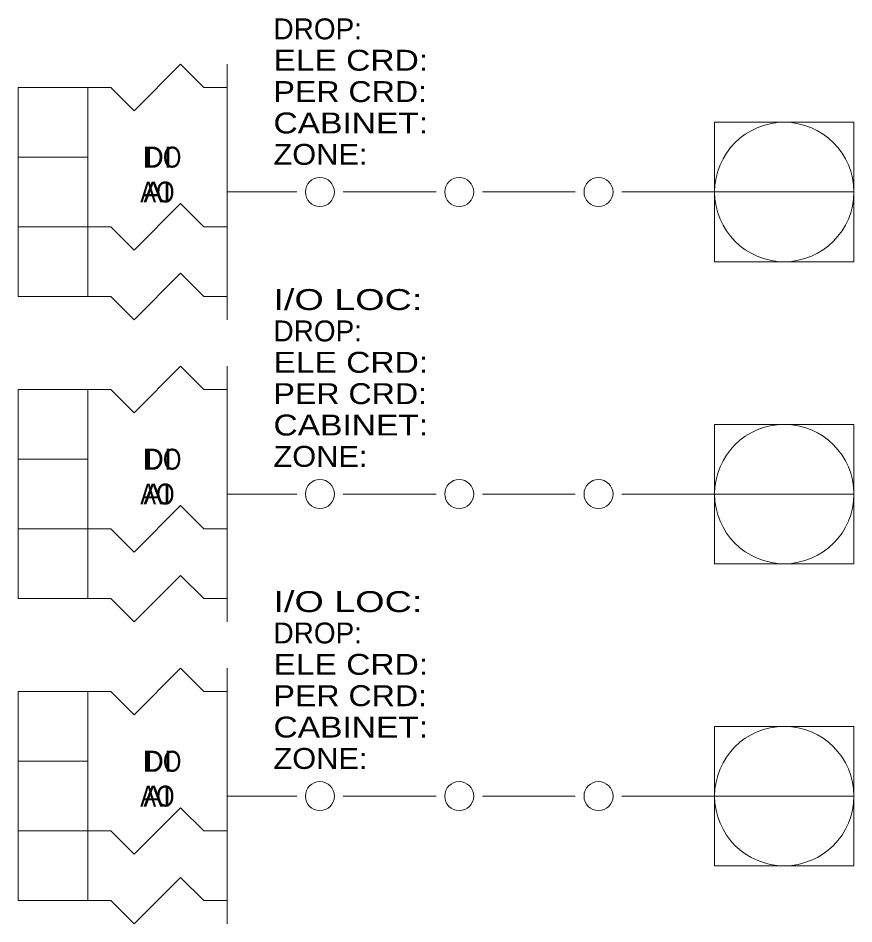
# Model space of a CAD drawing. Extents: x 0.01 to 1.26, y 0 to 0.83.
# Drawn here: x 0.9583 to 1.2583, y 0.1708 to 0.4957 of the extents above; entities that cross this region are included whole.
import ezdxf
from ezdxf.enums import TextEntityAlignment as Align

# ---------------------------------------------------------------- set-up
doc = ezdxf.new("R2010")
doc.units = 0
doc.header["$LTSCALE"] = 0.003
for name, color, linetype, lineweight in [('31', 7, 'Continuous', 13), ('32', 7, 'Continuous', 13), ('33', 7, 'Continuous', 13), ('34', 7, 'Continuous', 13), ('39', 7, 'Continuous', 13), ('40', 7, 'Continuous', 13), ('41', 7, 'Continuous', 13), ('42', 7, 'Continuous', 13), ('43', 7, 'Continuous', 13), ('44', 7, 'Continuous', 13), ('49', 7, 'Continuous', 13), ('50', 7, 'Continuous', 13), ('51', 7, 'Continuous', 13), ('52', 7, 'Continuous', 13), ('53', 7, 'Continuous', 13), ('54', 7, 'Continuous', 13), ('59', 7, 'Continuous', 13), ('60', 7, 'Continuous', 13)]:
    doc.layers.add(name, color=color, linetype=linetype, lineweight=lineweight)

msp = doc.modelspace()

# ---------------------------------------------------------------- linework, layer by layer
at = {"layer": '31'}
msp.add_line((1.033333, 0.479166), (1.033333, 0.4125), dxfattribs=at)
for points in [[(0.983333, 0.470833), (0.991666, 0.470833), (1, 0.4625), (1.016666, 0.479166), (1.025, 0.470833), (1.033333, 0.470833)], [(0.958333, 0.445833), (0.958333, 0.420833), (0.983333, 0.420833), (0.983333, 0.445833)], [(0.983333, 0.420833), (0.991666, 0.420833), (1, 0.4125), (1.016666, 0.429166), (1.025, 0.420833), (1.033333, 0.420833)]]:
    msp.add_lwpolyline(points, dxfattribs=at)
msp.add_lwpolyline([(0.958333, 0.470833), (0.983333, 0.470833), (0.983333, 0.445833), (0.958333, 0.445833)], close=True, dxfattribs=at)
at = {"layer": '32'}
for p, q in [((1.033333, 0.479166), (1.033333, 0.4125)), ((0.958333, 0.445833), (0.983333, 0.445833))]:
    msp.add_line(p, q, dxfattribs=at)
for points in [[(0.983333, 0.470833), (0.991666, 0.470833), (1, 0.4625), (1.016666, 0.479166), (1.025, 0.470833), (1.033333, 0.470833)], [(0.983333, 0.420833), (0.991666, 0.420833), (1, 0.4125), (1.016666, 0.429166), (1.025, 0.420833), (1.033333, 0.420833)]]:
    msp.add_lwpolyline(points, dxfattribs=at)
msp.add_lwpolyline([(0.958333, 0.470833), (0.983333, 0.470833), (0.983333, 0.420833), (0.958333, 0.420833)], close=True, dxfattribs=at)
at = {"layer": '33'}
for p, q in [((1.033333, 0.3875), (1.033333, 0.479166)), ((0.958333, 0.445833), (0.983333, 0.445833)), ((0.958333, 0.420833), (0.983333, 0.420833))]:
    msp.add_line(p, q, dxfattribs=at)
for points in [[(0.983333, 0.470833), (0.991666, 0.470833), (1, 0.4625), (1.016666, 0.479166), (1.025, 0.470833), (1.033333, 0.470833)], [(0.983333, 0.395833), (0.991666, 0.395833), (1, 0.3875), (1.016666, 0.404166), (1.025, 0.395833), (1.033333, 0.395833)]]:
    msp.add_lwpolyline(points, dxfattribs=at)
msp.add_lwpolyline([(0.958333, 0.470833), (0.983333, 0.470833), (0.983333, 0.395833), (0.958333, 0.395833)], close=True, dxfattribs=at)
at = {"layer": '34'}
for p, q in [((1.033333, 0.3875), (1.033333, 0.479166)), ((0.958333, 0.445833), (0.983333, 0.445833)), ((0.958333, 0.420833), (0.983333, 0.420833))]:
    msp.add_line(p, q, dxfattribs=at)
for points in [[(0.983333, 0.470833), (0.991666, 0.470833), (1, 0.4625), (1.016666, 0.479166), (1.025, 0.470833), (1.033333, 0.470833)], [(0.983333, 0.395833), (0.991666, 0.395833), (1, 0.3875), (1.016666, 0.404166), (1.025, 0.395833), (1.033333, 0.395833)]]:
    msp.add_lwpolyline(points, dxfattribs=at)
msp.add_lwpolyline([(0.958333, 0.470833), (0.983333, 0.470833), (0.983333, 0.395833), (0.958333, 0.395833)], close=True, dxfattribs=at)
at = {"layer": '39'}
for p, q in [((1.058333, 0.433333), (1.033333, 0.433333)), ((1.108333, 0.433333), (1.075, 0.433333)), ((1.158333, 0.433333), (1.125, 0.433333)), ((1.208333, 0.433333), (1.175, 0.433333)), ((1.208333, 0.433333), (1.258333, 0.433333))]:
    msp.add_line(p, q, dxfattribs=at)
msp.add_lwpolyline([(1.208333, 0.458333), (1.208333, 0.408333), (1.258333, 0.408333), (1.258333, 0.458333)], close=True, dxfattribs=at)
for centre, radius in [((1.233333, 0.433333), 0.025), ((1.066666, 0.433333), 0.005208), ((1.116666, 0.433333), 0.005208), ((1.166666, 0.433333), 0.005208)]:
    msp.add_circle(centre, radius, dxfattribs=at)
at = {"layer": '40'}
for p, q in [((1.058333, 0.433333), (1.033333, 0.433333)), ((1.108333, 0.433333), (1.075, 0.433333)), ((1.158333, 0.433333), (1.125, 0.433333)), ((1.208333, 0.433333), (1.175, 0.433333)), ((1.208333, 0.433333), (1.258333, 0.433333))]:
    msp.add_line(p, q, dxfattribs=at)
msp.add_lwpolyline([(1.208333, 0.458333), (1.208333, 0.408333), (1.258333, 0.408333), (1.258333, 0.458333)], close=True, dxfattribs=at)
for centre, radius in [((1.233333, 0.433333), 0.025), ((1.066666, 0.433333), 0.005208), ((1.116666, 0.433333), 0.005208), ((1.166666, 0.433333), 0.005208)]:
    msp.add_circle(centre, radius, dxfattribs=at)
at = {"layer": '41'}
msp.add_line((1.033333, 0.370833), (1.033333, 0.304166), dxfattribs=at)
for points in [[(0.983333, 0.3625), (0.991666, 0.3625), (1, 0.354166), (1.016666, 0.370833), (1.025, 0.3625), (1.033333, 0.3625)], [(0.958333, 0.3375), (0.958333, 0.3125), (0.983333, 0.3125), (0.983333, 0.3375)], [(0.983333, 0.3125), (0.991666, 0.3125), (1, 0.304166), (1.016666, 0.320833), (1.025, 0.3125), (1.033333, 0.3125)]]:
    msp.add_lwpolyline(points, dxfattribs=at)
msp.add_lwpolyline([(0.958333, 0.3625), (0.983333, 0.3625), (0.983333, 0.3375), (0.958333, 0.3375)], close=True, dxfattribs=at)
at = {"layer": '42'}
for p, q in [((1.033333, 0.370833), (1.033333, 0.304166)), ((0.958333, 0.3375), (0.983333, 0.3375))]:
    msp.add_line(p, q, dxfattribs=at)
for points in [[(0.983333, 0.3625), (0.991666, 0.3625), (1, 0.354166), (1.016666, 0.370833), (1.025, 0.3625), (1.033333, 0.3625)], [(0.983333, 0.3125), (0.991666, 0.3125), (1, 0.304166), (1.016666, 0.320833), (1.025, 0.3125), (1.033333, 0.3125)]]:
    msp.add_lwpolyline(points, dxfattribs=at)
msp.add_lwpolyline([(0.958333, 0.3625), (0.983333, 0.3625), (0.983333, 0.3125), (0.958333, 0.3125)], close=True, dxfattribs=at)
at = {"layer": '43'}
for p, q in [((1.033333, 0.279166), (1.033333, 0.370833)), ((0.958333, 0.3375), (0.983333, 0.3375)), ((0.958333, 0.3125), (0.983333, 0.3125))]:
    msp.add_line(p, q, dxfattribs=at)
for points in [[(0.983333, 0.3625), (0.991666, 0.3625), (1, 0.354166), (1.016666, 0.370833), (1.025, 0.3625), (1.033333, 0.3625)], [(0.983333, 0.2875), (0.991666, 0.2875), (1, 0.279166), (1.016666, 0.295833), (1.025, 0.2875), (1.033333, 0.2875)]]:
    msp.add_lwpolyline(points, dxfattribs=at)
msp.add_lwpolyline([(0.958333, 0.3625), (0.983333, 0.3625), (0.983333, 0.2875), (0.958333, 0.2875)], close=True, dxfattribs=at)
at = {"layer": '44'}
for p, q in [((1.033333, 0.279166), (1.033333, 0.370833)), ((0.958333, 0.3375), (0.983333, 0.3375)), ((0.958333, 0.3125), (0.983333, 0.3125))]:
    msp.add_line(p, q, dxfattribs=at)
for points in [[(0.983333, 0.3625), (0.991666, 0.3625), (1, 0.354166), (1.016666, 0.370833), (1.025, 0.3625), (1.033333, 0.3625)], [(0.983333, 0.2875), (0.991666, 0.2875), (1, 0.279166), (1.016666, 0.295833), (1.025, 0.2875), (1.033333, 0.2875)]]:
    msp.add_lwpolyline(points, dxfattribs=at)
msp.add_lwpolyline([(0.958333, 0.3625), (0.983333, 0.3625), (0.983333, 0.2875), (0.958333, 0.2875)], close=True, dxfattribs=at)
at = {"layer": '49'}
for p, q in [((1.058333, 0.325), (1.033333, 0.325)), ((1.108333, 0.325), (1.075, 0.325)), ((1.158333, 0.325), (1.125, 0.325)), ((1.208333, 0.325), (1.175, 0.325)), ((1.208333, 0.325), (1.258333, 0.325))]:
    msp.add_line(p, q, dxfattribs=at)
msp.add_lwpolyline([(1.208333, 0.35), (1.208333, 0.3), (1.258333, 0.3), (1.258333, 0.35)], close=True, dxfattribs=at)
for centre, radius in [((1.233333, 0.325), 0.025), ((1.066666, 0.325), 0.005208), ((1.116666, 0.325), 0.005208), ((1.166666, 0.325), 0.005208)]:
    msp.add_circle(centre, radius, dxfattribs=at)
at = {"layer": '50'}
for p, q in [((1.058333, 0.325), (1.033333, 0.325)), ((1.108333, 0.325), (1.075, 0.325)), ((1.158333, 0.325), (1.125, 0.325)), ((1.208333, 0.325), (1.175, 0.325)), ((1.208333, 0.325), (1.258333, 0.325))]:
    msp.add_line(p, q, dxfattribs=at)
msp.add_lwpolyline([(1.208333, 0.35), (1.208333, 0.3), (1.258333, 0.3), (1.258333, 0.35)], close=True, dxfattribs=at)
for centre, radius in [((1.233333, 0.325), 0.025), ((1.066666, 0.325), 0.005208), ((1.116666, 0.325), 0.005208), ((1.166666, 0.325), 0.005208)]:
    msp.add_circle(centre, radius, dxfattribs=at)
at = {"layer": '51'}
msp.add_line((1.033333, 0.2625), (1.033333, 0.195833), dxfattribs=at)
for points in [[(0.983333, 0.254166), (0.991666, 0.254166), (1, 0.245833), (1.016666, 0.2625), (1.025, 0.254166), (1.033333, 0.254166)], [(0.958333, 0.229166), (0.958333, 0.204166), (0.983333, 0.204166), (0.983333, 0.229166)], [(0.983333, 0.204166), (0.991666, 0.204166), (1, 0.195833), (1.016666, 0.2125), (1.025, 0.204166), (1.033333, 0.204166)]]:
    msp.add_lwpolyline(points, dxfattribs=at)
msp.add_lwpolyline([(0.958333, 0.254166), (0.983333, 0.254166), (0.983333, 0.229166), (0.958333, 0.229166)], close=True, dxfattribs=at)
at = {"layer": '52'}
for p, q in [((1.033333, 0.2625), (1.033333, 0.195833)), ((0.958333, 0.229166), (0.983333, 0.229166))]:
    msp.add_line(p, q, dxfattribs=at)
for points in [[(0.983333, 0.254166), (0.991666, 0.254166), (1, 0.245833), (1.016666, 0.2625), (1.025, 0.254166), (1.033333, 0.254166)], [(0.983333, 0.204166), (0.991666, 0.204166), (1, 0.195833), (1.016666, 0.2125), (1.025, 0.204166), (1.033333, 0.204166)]]:
    msp.add_lwpolyline(points, dxfattribs=at)
msp.add_lwpolyline([(0.958333, 0.254166), (0.983333, 0.254166), (0.983333, 0.204166), (0.958333, 0.204166)], close=True, dxfattribs=at)
at = {"layer": '53'}
for p, q in [((1.033333, 0.170833), (1.033333, 0.2625)), ((0.958333, 0.229166), (0.983333, 0.229166)), ((0.958333, 0.204166), (0.983333, 0.204166))]:
    msp.add_line(p, q, dxfattribs=at)
for points in [[(0.983333, 0.254166), (0.991666, 0.254166), (1, 0.245833), (1.016666, 0.2625), (1.025, 0.254166), (1.033333, 0.254166)], [(0.983333, 0.179166), (0.991666, 0.179166), (1, 0.170833), (1.016666, 0.1875), (1.025, 0.179166), (1.033333, 0.179166)]]:
    msp.add_lwpolyline(points, dxfattribs=at)
msp.add_lwpolyline([(0.958333, 0.254166), (0.983333, 0.254166), (0.983333, 0.179166), (0.958333, 0.179166)], close=True, dxfattribs=at)
at = {"layer": '54'}
for p, q in [((1.033333, 0.170833), (1.033333, 0.2625)), ((0.958333, 0.229166), (0.983333, 0.229166)), ((0.958333, 0.204166), (0.983333, 0.204166))]:
    msp.add_line(p, q, dxfattribs=at)
for points in [[(0.983333, 0.254166), (0.991666, 0.254166), (1, 0.245833), (1.016666, 0.2625), (1.025, 0.254166), (1.033333, 0.254166)], [(0.983333, 0.179166), (0.991666, 0.179166), (1, 0.170833), (1.016666, 0.1875), (1.025, 0.179166), (1.033333, 0.179166)]]:
    msp.add_lwpolyline(points, dxfattribs=at)
msp.add_lwpolyline([(0.958333, 0.254166), (0.983333, 0.254166), (0.983333, 0.179166), (0.958333, 0.179166)], close=True, dxfattribs=at)
at = {"layer": '59'}
for p, q in [((1.058333, 0.216666), (1.033333, 0.216666)), ((1.108333, 0.216666), (1.075, 0.216666)), ((1.158333, 0.216666), (1.125, 0.216666)), ((1.208333, 0.216666), (1.175, 0.216666)), ((1.208333, 0.216666), (1.258333, 0.216666))]:
    msp.add_line(p, q, dxfattribs=at)
msp.add_lwpolyline([(1.208333, 0.241666), (1.208333, 0.191666), (1.258333, 0.191666), (1.258333, 0.241666)], close=True, dxfattribs=at)
for centre, radius in [((1.233333, 0.216666), 0.025), ((1.066666, 0.216666), 0.005208), ((1.116666, 0.216666), 0.005208), ((1.166666, 0.216666), 0.005208)]:
    msp.add_circle(centre, radius, dxfattribs=at)
at = {"layer": '60'}
for p, q in [((1.058333, 0.216666), (1.033333, 0.216666)), ((1.108333, 0.216666), (1.075, 0.216666)), ((1.158333, 0.216666), (1.125, 0.216666)), ((1.208333, 0.216666), (1.175, 0.216666)), ((1.208333, 0.216666), (1.258333, 0.216666))]:
    msp.add_line(p, q, dxfattribs=at)
msp.add_lwpolyline([(1.208333, 0.241666), (1.208333, 0.191666), (1.258333, 0.191666), (1.258333, 0.241666)], close=True, dxfattribs=at)
for centre, radius in [((1.233333, 0.216666), 0.025), ((1.066666, 0.216666), 0.005208), ((1.116666, 0.216666), 0.005208), ((1.166666, 0.216666), 0.005208)]:
    msp.add_circle(centre, radius, dxfattribs=at)

# ---------------------------------------------------------------- texts
at = {"layer": '31', "width": 1.05}
msp.add_text('DI', height=0.0075, dxfattribs=at).set_placement((1.008291, 0.442083), align=Align.CENTER)
at = {"layer": '32', "width": 0.85}
msp.add_text('DO', height=0.0075, dxfattribs=at).set_placement((1.004166, 0.442083))
at = {"layer": '33', "width": 1.05}
msp.add_text('AI', height=0.0075, dxfattribs=at).set_placement((1.008291, 0.429583), align=Align.CENTER)
at = {"layer": '34', "width": 0.85}
msp.add_text('AO', height=0.0075, dxfattribs=at).set_placement((1.008333, 0.429583), align=Align.CENTER)
at = {"layer": '39'}
msp.add_text('DROP:', height=0.0075, dxfattribs=at).set_placement((1.05, 0.488083))
for s, width, p in [('ELE CRD:', 1.2, (1.05, 0.476833)), ('PER CRD:', 1.15, (1.05, 0.465583)), ('CABINET:', 1.2, (1.05, 0.454333)), ('ZONE:', 1.1, (1.05, 0.443083))]:
    msp.add_text(s, height=0.0075, dxfattribs=dict(at, width=width)).set_placement(p)
at = {"layer": '40'}
msp.add_text('DROP:', height=0.0075, dxfattribs=at).set_placement((1.05, 0.488083))
for s, width, p in [('ELE CRD:', 1.2, (1.05, 0.476833)), ('PER CRD:', 1.15, (1.05, 0.465583)), ('CABINET:', 1.2, (1.05, 0.454333)), ('ZONE:', 1.1, (1.05, 0.443083))]:
    msp.add_text(s, height=0.0075, dxfattribs=dict(at, width=width)).set_placement(p)
at = {"layer": '41', "width": 1.05}
msp.add_text('DI', height=0.0075, dxfattribs=at).set_placement((1.008291, 0.33375), align=Align.CENTER)
at = {"layer": '42', "width": 0.85}
msp.add_text('DO', height=0.0075, dxfattribs=at).set_placement((1.004166, 0.33375))
at = {"layer": '43', "width": 1.05}
msp.add_text('AI', height=0.0075, dxfattribs=at).set_placement((1.008291, 0.32125), align=Align.CENTER)
at = {"layer": '44', "width": 0.85}
msp.add_text('AO', height=0.0075, dxfattribs=at).set_placement((1.008333, 0.32125), align=Align.CENTER)
at = {"layer": '49'}
for s, width, p in [('I/O LOC:', 1.35, (1.05, 0.391)), ('ELE CRD:', 1.2, (1.05, 0.3685)), ('PER CRD:', 1.15, (1.05, 0.35725)), ('CABINET:', 1.2, (1.05, 0.346)), ('ZONE:', 1.1, (1.05, 0.33475))]:
    msp.add_text(s, height=0.0075, dxfattribs=dict(at, width=width)).set_placement(p)
msp.add_text('DROP:', height=0.0075, dxfattribs=at).set_placement((1.05, 0.37975))
at = {"layer": '50'}
for s, width, p in [('I/O LOC:', 1.35, (1.05, 0.391)), ('ELE CRD:', 1.2, (1.05, 0.3685)), ('PER CRD:', 1.15, (1.05, 0.35725)), ('CABINET:', 1.2, (1.05, 0.346)), ('ZONE:', 1.1, (1.05, 0.33475))]:
    msp.add_text(s, height=0.0075, dxfattribs=dict(at, width=width)).set_placement(p)
msp.add_text('DROP:', height=0.0075, dxfattribs=at).set_placement((1.05, 0.37975))
at = {"layer": '51', "width": 1.05}
msp.add_text('DI', height=0.0075, dxfattribs=at).set_placement((1.008291, 0.225416), align=Align.CENTER)
at = {"layer": '52', "width": 0.85}
msp.add_text('DO', height=0.0075, dxfattribs=at).set_placement((1.004166, 0.225416))
at = {"layer": '53', "width": 1.05}
msp.add_text('AI', height=0.0075, dxfattribs=at).set_placement((1.008291, 0.212916), align=Align.CENTER)
at = {"layer": '54', "width": 0.85}
msp.add_text('AO', height=0.0075, dxfattribs=at).set_placement((1.008333, 0.212916), align=Align.CENTER)
at = {"layer": '59'}
for s, width, p in [('I/O LOC:', 1.35, (1.05, 0.282666)), ('ELE CRD:', 1.2, (1.05, 0.260166)), ('PER CRD:', 1.15, (1.05, 0.248916)), ('CABINET:', 1.2, (1.05, 0.237666)), ('ZONE:', 1.1, (1.05, 0.226416))]:
    msp.add_text(s, height=0.0075, dxfattribs=dict(at, width=width)).set_placement(p)
msp.add_text('DROP:', height=0.0075, dxfattribs=at).set_placement((1.05, 0.271416))
at = {"layer": '60'}
for s, width, p in [('I/O LOC:', 1.35, (1.05, 0.282666)), ('ELE CRD:', 1.2, (1.05, 0.260166)), ('PER CRD:', 1.15, (1.05, 0.248916)), ('CABINET:', 1.2, (1.05, 0.237666)), ('ZONE:', 1.1, (1.05, 0.226416))]:
    msp.add_text(s, height=0.0075, dxfattribs=dict(at, width=width)).set_placement(p)
msp.add_text('DROP:', height=0.0075, dxfattribs=at).set_placement((1.05, 0.271416))

doc.saveas('drawing.dxf')
